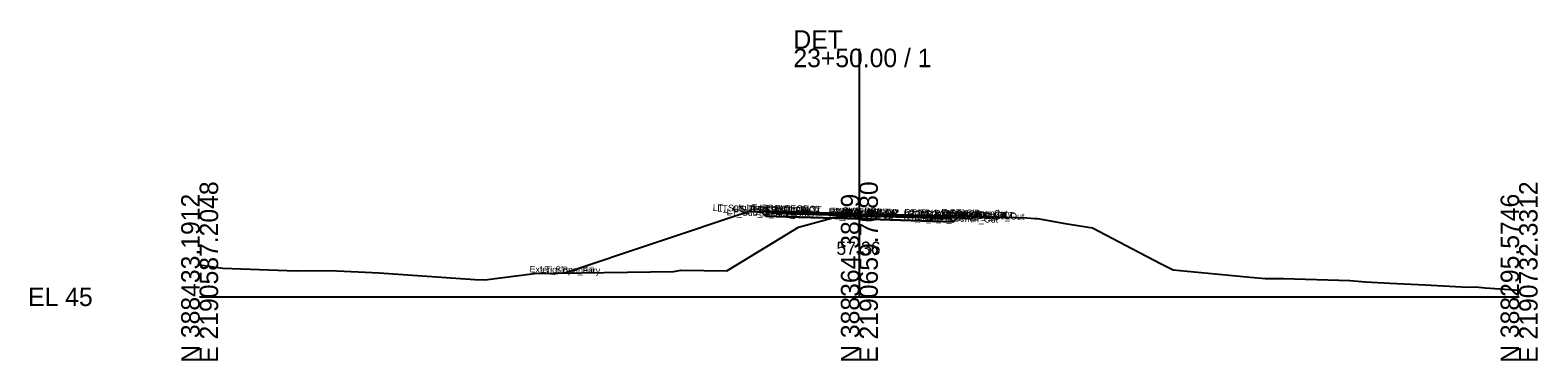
# Model space of a CAD drawing. Extents: x -26 to 1203, y -10 to 9543.
# Drawn here: x 974.3 to 1202.8, y 3490.3 to 3540.4 of the extents above; entities that cross this region are included whole.
import ezdxf

# ---------------------------------------------------------------- set-up
doc = ezdxf.new("R2010")
doc.units = 0
for name, color, linetype in [('Default', 7, 'Continuous'), ('Exist Cross Section Cell', 7, 'Continuous'), ('Exist XS Center Line Elevation Label', 7, 'Continuous'), ('Exist XS Ground Line', 7, 'Continuous'), ('Prop CMT Pvmt Course 1', 7, 'Continuous'), ('Prop CMT Pvmt Course 2', 7, 'Continuous'), ('Prop CMT Pvmt Course 3', 7, 'Continuous'), ('Prop CMT Pvmt Surface', 7, 'Continuous'), ('Prop CMT Pvmt Surface Shoulder', 7, 'Continuous'), ('Prop CMT Shld Paved Course 1', 7, 'Continuous'), ('Prop CMT Shld Paved Course 2', 7, 'Continuous'), ('Prop CMT Shld Paved Course 3', 7, 'Continuous'), ('Prop CMT Slope Grass', 7, 'Continuous'), ('Prop CMT Subgrade Earthwork', 7, 'Continuous'), ('Scratch_Level_0', 7, 'Continuous')]:
    doc.layers.add(name, color=color, linetype=linetype)

msp = doc.modelspace()

# ---------------------------------------------------------------- linework, layer by layer
at = {"layer": 'Exist Cross Section Cell'}
for p, q in [((1100, 3500), (1100, 3537.58)), ((1000, 3500), (1100, 3500)), ((1100, 3500), (1200, 3500))]:
    msp.add_line(p, q, dxfattribs=at)
at = {"layer": 'Exist XS Ground Line'}
for p, q in [((1088.06, 3508.89), (1090.75, 3510.56)), ((1090.75, 3510.56), (1091.87, 3510.86)), ((1091.87, 3510.86), (1096.33, 3512.04)), ((1096.33, 3512.04), (1097.29, 3512.1)), ((1097.29, 3512.1), (1100, 3512.36)), ((1100, 3512.36), (1100.92, 3512.46)), ((1100.92, 3512.46), (1101.45, 3512.51)), ((1101.45, 3512.51), (1102.52, 3512.51)), ((1102.52, 3512.51), (1103.02, 3512.53)), ((1103.02, 3512.53), (1113.36, 3512.31)), ((1113.36, 3512.31), (1114.3, 3512.3)), ((1114.3, 3512.3), (1115.04, 3512.28)), ((1115.04, 3512.28), (1125.38, 3511.96)), ((1125.38, 3511.96), (1126, 3511.92)), ((1126, 3511.92), (1126.58, 3511.87)), ((1126.58, 3511.87), (1127, 3511.84)), ((1127, 3511.84), (1131.2, 3511.08)), ((1131.2, 3511.08), (1135.33, 3510.43)), ((1135.33, 3510.43), (1141.42, 3507.27)), ((1079.93, 3503.96), (1088.06, 3508.89)), ((1141.42, 3507.27), (1145.76, 3504.99)), ((1000, 3504.82), (1003.49, 3504.35)), ((1003.49, 3504.35), (1014.62, 3503.94)), ((1014.62, 3503.94), (1019.75, 3503.99)), ((1019.75, 3503.99), (1027.22, 3503.64)), ((1027.22, 3503.64), (1041.72, 3502.61)), ((1043.21, 3502.57), (1050.76, 3503.52)), ((1050.76, 3503.52), (1071.85, 3503.82)), ((1071.85, 3503.82), (1072.96, 3504.03)), ((1072.96, 3504.03), (1079.93, 3503.96)), ((1145.76, 3504.99), (1147.54, 3504.07)), ((1147.54, 3504.07), (1159.22, 3502.99)), ((1041.72, 3502.61), (1043.21, 3502.57)), ((1159.22, 3502.99), (1161.49, 3502.79)), ((1161.49, 3502.79), (1164.31, 3502.79)), ((1164.31, 3502.79), (1174.33, 3502.46)), ((1174.33, 3502.46), (1176.73, 3502.28)), ((1176.73, 3502.28), (1180.39, 3502.09)), ((1180.39, 3502.09), (1185.74, 3501.84)), ((1185.74, 3501.84), (1192.16, 3501.48)), ((1192.16, 3501.48), (1193.46, 3501.5)), ((1193.46, 3501.5), (1194.87, 3501.34)), ((1194.87, 3501.34), (1200, 3501))]:
    msp.add_line(p, q, dxfattribs=at)
at = {"layer": 'Prop CMT Pvmt Course 1'}
for points in [[(1100, 3512.54), (1089, 3512.87)], [(1089, 3512.87), (1089, 3512.62)], [(1089, 3512.62), (1100, 3512.29)], [(1100, 3512.29), (1100, 3512.54)], [(1100, 3512.54), (1111, 3512.21)], [(1100, 3512.29), (1100, 3512.54)], [(1111, 3511.96), (1100, 3512.29)], [(1111, 3512.21), (1111, 3511.96)]]:
    msp.add_lwpolyline(points, dxfattribs=at)
msp.add_lwpolyline([(1100, 3512.29), (1100, 3512.41), (1100, 3512.41), (1100, 3512.29)], close=True, dxfattribs=at)
msp.add_lwpolyline([(1100, 3512.29), (1100, 3512.41), (1100, 3512.41), (1100, 3512.29)], close=True, dxfattribs=at)
at = {"layer": 'Prop CMT Pvmt Course 2'}
for points in [[(1089, 3512.62), (1100, 3512.29)], [(1100, 3512.29), (1089, 3512.62)], [(1089, 3512.62), (1089, 3512.62)], [(1100, 3512.29), (1100, 3512.29)], [(1111, 3511.96), (1100, 3512.29)], [(1100, 3512.29), (1100, 3512.29)], [(1100, 3512.29), (1111, 3511.96)], [(1111, 3511.96), (1111, 3511.96)]]:
    msp.add_lwpolyline(points, dxfattribs=at)
at = {"layer": 'Prop CMT Pvmt Course 3'}
for points in [[(1100, 3512.29), (1089, 3512.62)], [(1089, 3512.62), (1089, 3512.12)], [(1089, 3512.12), (1100, 3511.79)], [(1100, 3511.79), (1100, 3512.29)], [(1100, 3512.29), (1111, 3511.96)], [(1100, 3511.79), (1100, 3512.29)], [(1111, 3511.46), (1100, 3511.79)], [(1111, 3511.96), (1111, 3511.46)]]:
    msp.add_lwpolyline(points, dxfattribs=at)
at = {"layer": 'Prop CMT Pvmt Surface'}
for points in [[(1100, 3512.54), (1089, 3512.87)], [(1100, 3512.54), (1111, 3512.21)]]:
    msp.add_lwpolyline(points, dxfattribs=at)
at = {"layer": 'Prop CMT Pvmt Surface Shoulder'}
for points in [[(1089, 3512.87), (1087, 3512.93)], [(1111, 3512.21), (1113, 3512.15)]]:
    msp.add_lwpolyline(points, dxfattribs=at)
at = {"layer": 'Prop CMT Shld Paved Course 1'}
for points in [[(1089, 3512.87), (1087, 3512.93), (1086.76, 3512.68)], [(1086.76, 3512.68), (1089, 3512.62)], [(1089, 3512.62), (1089, 3512.87)], [(1111, 3512.21), (1113, 3512.15), (1113.26, 3511.89)], [(1111, 3511.96), (1111, 3512.21)], [(1113.26, 3511.89), (1111, 3511.96)]]:
    msp.add_lwpolyline(points, dxfattribs=at)
at = {"layer": 'Prop CMT Shld Paved Course 2'}
for points in [[(1089, 3512.62), (1086.76, 3512.68)], [(1086.76, 3512.68), (1086.76, 3512.68)], [(1086.76, 3512.68), (1089, 3512.62)], [(1089, 3512.62), (1089, 3512.62)], [(1111, 3511.96), (1113.26, 3511.89)], [(1113.26, 3511.89), (1111, 3511.96)], [(1111, 3511.96), (1111, 3511.96)], [(1113.26, 3511.89), (1113.26, 3511.89)]]:
    msp.add_lwpolyline(points, dxfattribs=at)
at = {"layer": 'Prop CMT Shld Paved Course 3'}
for points in [[(1089, 3512.62), (1086.76, 3512.68), (1086.26, 3512.7), (1085.77, 3512.21)], [(1089, 3512.12), (1089, 3512.62)], [(1085.77, 3512.21), (1089, 3512.12)], [(1111, 3511.96), (1113.26, 3511.89), (1113.76, 3511.87), (1114.27, 3511.36)], [(1111, 3511.46), (1111, 3511.96)], [(1114.27, 3511.36), (1111, 3511.46)]]:
    msp.add_lwpolyline(points, dxfattribs=at)
at = {"layer": 'Prop CMT Slope Grass'}
for points in [[(1087, 3512.93), (1083, 3512.81), (1055.34, 3503.59)], [(1113, 3512.15), (1117, 3511.83), (1117.01, 3511.82), (1117.75, 3512.19)]]:
    msp.add_lwpolyline(points, dxfattribs=at)
at = {"layer": 'Prop CMT Subgrade Earthwork'}
for points in [[(1085.77, 3512.21), (1085.12, 3512.87)], [(1089, 3512.12), (1085.77, 3512.21)], [(1100, 3511.79), (1089, 3512.12)], [(1100, 3511.79), (1111, 3511.46)], [(1111, 3511.46), (1114.27, 3511.36)], [(1114.27, 3511.36), (1114.91, 3511.99)]]:
    msp.add_lwpolyline(points, dxfattribs=at)

# ---------------------------------------------------------------- texts
at = {"layer": 'Default'}
msp.add_text('-', height=0.0001, dxfattribs=at).set_placement((1000, 3500))
at = {"layer": 'Exist Cross Section Cell'}
for s, p in [('DET', (1090, 3537.58)), ('23+50.00 / 1', (1090, 3534.78)), ('EL 45', (974, 3498.6))]:
    msp.add_text(s, height=2.8, dxfattribs=at).set_placement(p)
for s, p in [('E 2190587.2048', (1002.8, 3490)), ('E 2190659.7680', (1102.8, 3490)), ('E 2190732.3312', (1202.8, 3490)), ('N 388433.1912', (1000, 3490)), ('N 388364.3829', (1100, 3490)), ('N 388295.5746', (1200, 3490))]:
    msp.add_text(s, height=2.8, rotation=90, dxfattribs=at).set_placement(p)
at = {"layer": 'Exist XS Center Line Elevation Label'}
msp.add_text('57.36', height=2, dxfattribs=at).set_placement((1096.52, 3506.36))
at = {"layer": 'Scratch_Level_0'}
for s, p in [('LT_Sub_Trench_Out_DLT', (1077.77, 3513.01)), ('LT_GS_OS_CTL', (1078.46, 3512.89)), ('LT_Sub_Trench_Out', (1079.88, 3512.33)), ('LT_PS3_Shelf_Out', (1080.92, 3512.8)), ('LT_PS3_OEOP', (1082.54, 3512.77)), ('LT_PS2_OEOP', (1082.54, 3512.77)), ('LT_PS1_OEOP', (1082.91, 3513.01)), ('LT_PV2_OEOT', (1084.75, 3512.7)), ('LT_PV3_OEOT', (1084.75, 3512.7)), ('LT_Sub_OEOT', (1084.77, 3512.2)), ('LT_PV1_OEOT', (1084.87, 3512.95)), ('RT_PV2_OEEOP', (1095.33, 3512.38)), ('RT_PV3_OEEOP', (1095.33, 3512.38)), ('RT_Sub_OEEOP', (1095.36, 3511.88)), ('LT_PV2_OEEOP', (1095.39, 3512.38)), ('LT_PV3_OEEOP', (1095.39, 3512.38)), ('LT_Sub_OEEOP', (1095.42, 3511.87)), ('RT_PV1_OEEOP', (1095.45, 3512.5)), ('LT_PV1_OEEOP', (1095.51, 3512.5)), ('RT_PV2_IEEOP', (1095.71, 3512.37)), ('LT_PV2_IEEOP', (1095.77, 3512.37)), ('RT_PV1_IEEOP', (1095.83, 3512.49)), ('LT_PV1_IEEOP', (1095.89, 3512.49)), ('PV2_PGL', (1097.35, 3512.34)), ('PV1_PGL', (1097.47, 3512.58)), ('RT_PV3_OEOT', (1106.69, 3512.04)), ('RT_PV2_OEOT', (1106.69, 3512.04)), ('RT_PV1_OEOT', (1106.81, 3512.29)), ('RT_Sub_Trench_Out_DLT', (1107.5, 3512.14)), ('RT_PS3_Shelf_Out', (1108.36, 3511.98)), ('RT_PS1_OEOP', (1108.85, 3512.23)), ('RT_PS3_OEOP', (1108.99, 3511.97)), ('RT_PS2_OEOP', (1108.99, 3511.97)), ('RT_SS_Ditch_Base_Out', (1110.21, 3511.96)), ('Exterior Boundary', (1112.41, 3512.3)), ('RT_GS_OS_CTL', (1112.41, 3511.92)), ('RT_Slope_Cut', (1113.69, 3512.27)), ('RT_Sub_OEOT', (1106.71, 3511.54)), ('RT_Sub_Trench_Out', (1108.32, 3511.47)), ('Exterior Boundary', (1050, 3503.69)), ('LT_Slope_Fill', (1051.58, 3503.66))]:
    msp.add_text(s, height=1, rotation=358.8836, dxfattribs=at).set_placement(p)

doc.saveas('drawing.dxf')
